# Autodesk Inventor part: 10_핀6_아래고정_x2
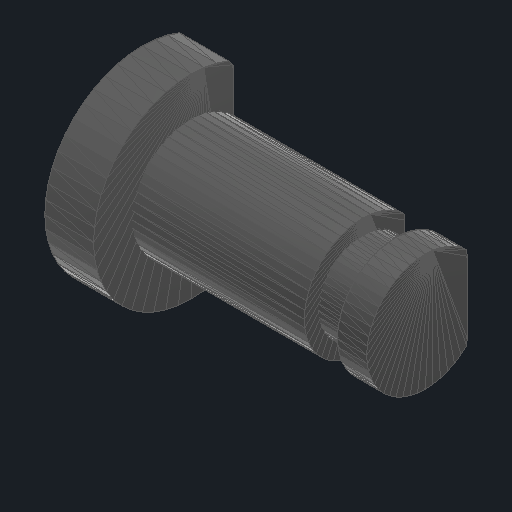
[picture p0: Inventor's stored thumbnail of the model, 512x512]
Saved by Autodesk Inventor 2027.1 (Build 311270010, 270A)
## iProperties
Created: 2026-11
Part Number: 10_핀6_아래고정_x2
Material: 일반
Document SubType Name: Modeling
Designer: djshs
Density: 1 g/cm^3
Appearance: 기본값
Author: djshs
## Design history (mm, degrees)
node "10_핀6_아래고정_x2"
  node "MeshFeature1"
